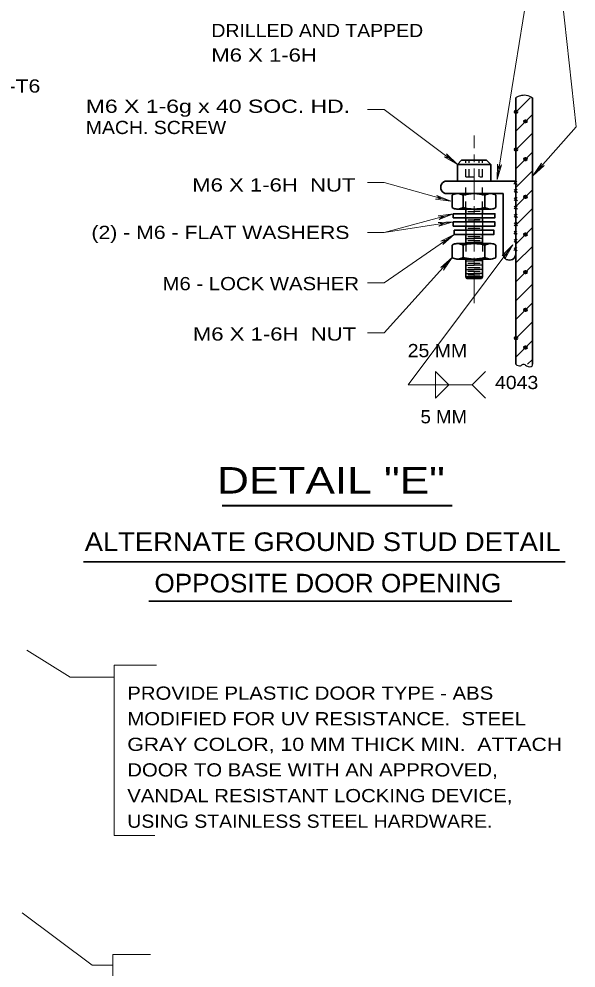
# Model space of a CAD drawing. Extents: x 312583 to 312854, y 144419 to 144597.
# Drawn here: x 312761.7 to 312793.7, y 144484.7 to 144539.3 of the extents above; entities that cross this region are included whole.
import ezdxf

# ---------------------------------------------------------------- set-up
doc = ezdxf.new("R2010")
doc.units = 0
doc.header["$LTSCALE"] = 0.3
doc.header["$PDMODE"] = 32
doc.header["$PDSIZE"] = 0.15
doc.linetypes.add('LONG_DASH_SHORT_DASH', pattern=[9.9, 6, -1.2, 1.5, -1.2])
doc.linetypes.add('SHORT_DASHED', pattern=[2.7, 1.5, -1.2])
doc.layers.add('1', color=7, linetype='Continuous', lineweight=40)
doc.layers.add('2', color=7, linetype='Continuous', lineweight=13)

msp = doc.modelspace()

# ---------------------------------------------------------------- linework, layer by layer
at = {"layer": '1', "lineweight": 35}
for p, q in [((312790.2149, 144519.4765), (312790.2149, 144534.8099)), ((312791.1732, 144519.4765), (312791.1732, 144534.8099)), ((312786.8569, 144530.0182), (312786.8569, 144530.9765)), ((312788.5359, 144531.2142), (312788.7735, 144530.9765)), ((312790.2149, 144530.0182), (312786.2589, 144530.0182)), ((312789.4942, 144529.2975), (312786.2589, 144529.2975)), ((312786.5579, 144529.2132), (312786.5579, 144528.4925)), ((312786.8339, 144529.2975), (312787.8152, 144529.2975)), ((312787.1865, 144529.2132), (312787.1865, 144528.4925)), ((312788.7965, 144529.2975), (312787.8152, 144529.2975)), ((312788.4439, 144529.2132), (312788.4439, 144528.4925)), ((312789.0725, 144529.2132), (312789.0725, 144528.4925)), ((312789.4942, 144525.8245), (312789.4942, 144529.2975)), ((312786.8339, 144528.4005), (312787.8152, 144528.4005)), ((312787.3399, 144528.3852), (312787.3399, 144528.1475)), ((312788.7965, 144528.4005), (312787.8152, 144528.4005)), ((312788.2982, 144528.3852), (312788.2982, 144528.1475)), ((312787.3399, 144527.9022), (312787.3399, 144527.6722)), ((312788.2982, 144527.9022), (312788.2982, 144527.6722)), ((312787.3399, 144527.4345), (312787.3399, 144527.1892)), ((312788.2982, 144527.4345), (312788.2982, 144527.1892)), ((312787.3399, 144526.9515), (312787.3399, 144526.4225)), ((312788.2982, 144526.9515), (312788.2982, 144526.4225)), ((312786.5579, 144526.3382), (312786.5579, 144525.6175)), ((312786.8339, 144526.4225), (312787.8152, 144526.4225)), ((312787.1865, 144526.3382), (312787.1865, 144525.6175)), ((312788.7965, 144526.4225), (312787.8152, 144526.4225)), ((312788.4439, 144526.3382), (312788.4439, 144525.6175)), ((312789.0725, 144526.3382), (312789.0725, 144525.6175)), ((312786.8339, 144525.5255), (312787.8152, 144525.5255)), ((312787.3399, 144525.5255), (312787.3399, 144524.4982)), ((312788.7965, 144525.5255), (312787.8152, 144525.5255)), ((312788.2982, 144525.5255), (312788.2982, 144524.4982)), ((312787.3399, 144524.4982), (312787.8152, 144524.4982)), ((312788.2982, 144524.4982), (312787.8152, 144524.4982))]:
    msp.add_line(p, q, dxfattribs=at)
at = {"layer": '1', "lineweight": 13}
for p, q in [((312790.2149, 144533.9742), (312791.0505, 144534.8099)), ((312790.2149, 144532.8932), (312791.1732, 144533.8515)), ((312790.2149, 144531.8045), (312791.1732, 144532.7629)), ((312790.2149, 144530.7235), (312791.1732, 144531.6819)), ((312790.2072, 144529.6349), (312791.1732, 144530.6009)), ((312790.2149, 144528.5539), (312791.1732, 144529.5122)), ((312790.2149, 144527.4729), (312791.1732, 144528.4312)), ((312790.2149, 144526.3842), (312791.1732, 144527.3425)), ((312790.2149, 144525.3032), (312791.1732, 144526.2615)), ((312790.2149, 144524.2222), (312791.1732, 144525.1729)), ((312790.2149, 144523.1335), (312791.1732, 144524.0919)), ((312790.2149, 144522.0449), (312791.1732, 144523.0109)), ((312790.2149, 144520.9639), (312791.1732, 144521.9222)), ((312790.2149, 144519.8829), (312791.1732, 144520.8412)), ((312790.8895, 144519.4765), (312791.1732, 144519.7525))]:
    msp.add_line(p, q, dxfattribs=at)
at = {"layer": '1', "linetype": 'LONG_DASH_SHORT_DASH', "lineweight": 13}
msp.add_line((312787.8152, 144522.9955), (312787.8152, 144532.6325), dxfattribs=at)
at = {"layer": '1', "linetype": 'SHORT_DASHED', "lineweight": 25}
for p, q in [((312787.3399, 144530.2559), (312787.3399, 144531.2142)), ((312787.5392, 144530.2559), (312787.5392, 144531.2142)), ((312788.1142, 144530.2559), (312788.1142, 144531.2142)), ((312788.2982, 144530.2559), (312788.2982, 144531.2142)), ((312787.3399, 144530.2559), (312788.2982, 144530.2559)), ((312787.3399, 144528.3852), (312787.3399, 144530.0182)), ((312788.2982, 144528.3852), (312788.2982, 144530.0182)), ((312787.3399, 144527.9022), (312787.3399, 144528.1475)), ((312788.2982, 144527.9022), (312788.2982, 144528.1475)), ((312787.3399, 144527.6722), (312787.3399, 144527.4345)), ((312788.2982, 144527.6722), (312788.2982, 144527.4345)), ((312787.3399, 144527.1892), (312787.3399, 144526.9515)), ((312788.2982, 144527.1892), (312788.2982, 144526.9515)), ((312787.3399, 144526.4225), (312787.3399, 144525.5255)), ((312788.2982, 144526.4225), (312788.2982, 144525.5255))]:
    msp.add_line(p, q, dxfattribs=at)
at = {"layer": '1', "lineweight": 25}
for p, q in [((312787.4549, 144528.2625), (312787.8152, 144528.2625)), ((312788.1755, 144528.2625), (312787.8152, 144528.2625)), ((312787.4549, 144527.7872), (312787.8152, 144527.7872)), ((312787.4549, 144527.7872), (312788.1755, 144527.7872)), ((312788.1755, 144527.7872), (312787.8152, 144527.7872)), ((312787.4549, 144527.3119), (312788.1755, 144527.3119)), ((312787.3322, 144526.7215), (312787.8152, 144526.7215)), ((312787.3322, 144526.4839), (312787.8152, 144526.4839)), ((312787.4549, 144526.8289), (312788.1755, 144526.8289)), ((312787.4549, 144526.5912), (312788.1755, 144526.5912)), ((312788.2982, 144526.7215), (312787.8152, 144526.7215)), ((312788.2982, 144526.4839), (312787.8152, 144526.4839)), ((312787.3322, 144525.4182), (312787.8152, 144525.4182)), ((312788.2982, 144525.4182), (312787.8152, 144525.4182)), ((312787.3322, 144525.1729), (312787.8152, 144525.1729)), ((312787.3322, 144524.9352), (312787.8152, 144524.9352)), ((312787.4549, 144525.2879), (312788.1755, 144525.2879)), ((312787.4549, 144525.0502), (312788.1755, 144525.0502)), ((312787.4549, 144524.8279), (312788.1755, 144524.8279)), ((312788.2982, 144525.1729), (312787.8152, 144525.1729)), ((312788.2982, 144524.9352), (312787.8152, 144524.9352)), ((312787.3322, 144524.6975), (312787.8152, 144524.6975)), ((312787.4549, 144524.6132), (312788.1755, 144524.6132)), ((312788.2982, 144524.6975), (312787.8152, 144524.6975))]:
    msp.add_line(p, q, dxfattribs=at)
at = {"layer": '1', "lineweight": 35}
for points in [[(312788.5359, 144531.2142), (312787.1022, 144531.2142), (312786.8569, 144530.9765)], [(312788.7735, 144530.0182), (312788.7735, 144530.9765), (312786.8569, 144530.9765)], [(312787.3399, 144524.4982), (312787.4012, 144524.4139), (312787.8152, 144524.4139)], [(312788.2982, 144524.4982), (312788.2369, 144524.4139), (312787.8152, 144524.4139)]]:
    msp.add_lwpolyline(points, dxfattribs=at)
for points in [[(312786.6192, 144528.1399), (312786.6192, 144527.9022), (312789.0189, 144527.9022), (312789.0189, 144528.1399)], [(312786.6192, 144527.6645), (312786.6192, 144527.4269), (312789.0189, 144527.4269), (312789.0189, 144527.6645)], [(312786.6805, 144527.1892), (312786.6805, 144526.9515), (312788.9575, 144526.9515), (312788.9575, 144527.1892)]]:
    msp.add_lwpolyline(points, close=True, dxfattribs=at)
for centre, radius, start, end in [((312786.257, 144529.6559), 0.3584, 89.69361, 270.30639), ((312786.8489, 144528.7785), 0.5187, 91.66257, 124.1297), ((312786.5984, 144527.8443), 1.4854, 66.63635, 78.22986), ((312787.8814, 144526.6186), 2.6807, 91.405, 105.00202), ((312787.7499, 144526.6186), 2.6807, 74.99798, 88.595), ((312789.0329, 144527.8443), 1.4854, 101.77014, 113.36365), ((312788.7824, 144528.7785), 0.5187, 55.8703, 88.33743), ((312786.8489, 144528.9215), 0.5187, 235.8703, 268.33743), ((312786.5984, 144529.8557), 1.4854, 281.77014, 293.36365), ((312787.8814, 144531.0814), 2.6807, 254.99798, 268.595), ((312787.7499, 144531.0814), 2.6807, 271.405, 285.00202), ((312789.0329, 144529.8557), 1.4854, 246.63635, 258.22986), ((312788.7824, 144528.9215), 0.5187, 271.66257, 304.1297), ((312786.8489, 144525.9035), 0.5187, 91.66257, 124.1297), ((312786.5984, 144524.9693), 1.4854, 66.63635, 78.22986), ((312787.8814, 144523.7436), 2.6807, 91.405, 105.00202), ((312787.7499, 144523.7436), 2.6807, 74.99798, 88.595), ((312789.0329, 144524.9693), 1.4854, 101.77014, 113.36365), ((312788.7824, 144525.9035), 0.5187, 55.8703, 88.33743), ((312786.8489, 144526.0465), 0.5187, 235.8703, 268.33743), ((312786.5984, 144526.9807), 1.4854, 281.77014, 293.36365), ((312787.8814, 144528.2064), 2.6807, 254.99798, 268.595), ((312787.7499, 144528.2064), 2.6807, 271.405, 285.00202), ((312789.0329, 144526.9807), 1.4854, 246.63635, 258.22986), ((312788.7824, 144526.0465), 0.5187, 271.66257, 304.1297), ((312789.8526, 144525.8226), 0.3584, 179.69361, 0.30639)]:
    msp.add_arc(centre, radius, start, end, dxfattribs=at)
at = {"layer": '1', "lineweight": 25}
for points in [[(312790.2149, 144534.8099), (312790.3682, 144534.9019), (312790.6365, 144534.9632), (312790.8129, 144534.9632), (312791.1732, 144534.8099)], [(312790.2149, 144519.4765), (312790.4909, 144519.3922), (312790.6365, 144519.4765), (312790.8359, 144519.3922), (312791.1579, 144519.3922), (312791.1732, 144519.4765)]]:
    msp.add_spline(points, degree=3, dxfattribs=at)
at = {"layer": '1'}
for p in [(312790.2302, 144533.9972), (312790.7745, 144533.4529), (312790.2302, 144531.8275), (312790.7745, 144531.2832), (312790.7745, 144529.1135), (312790.7745, 144526.9439), (312790.7745, 144524.7742), (312790.7745, 144522.6122), (312790.2302, 144520.9792), (312790.7745, 144520.4425)]:
    msp.add_point(p, dxfattribs=at)
at = {"layer": '2'}
for p, q in [((312789.1415, 144530.1102), (312790.9202, 144541.0582)), ((312782.6479, 144534.1429), (312781.6895, 144534.1429)), ((312782.6479, 144534.1429), (312786.8569, 144530.9765)), ((312786.1055, 144531.4135), (312786.3892, 144531.3292)), ((312786.8569, 144530.9765), (312786.1055, 144531.4135)), ((312786.2282, 144531.5822), (312786.3892, 144531.3292)), ((312786.8569, 144530.9765), (312786.2282, 144531.5822)), ((312789.1415, 144530.1102), (312789.1722, 144530.9842)), ((312789.1415, 144530.1102), (312789.3869, 144530.9459)), ((312789.1722, 144530.9842), (312789.2412, 144530.6929)), ((312789.3869, 144530.9459), (312789.2412, 144530.6929)), ((312791.2039, 144530.3249), (312791.6945, 144531.0455)), ((312791.2039, 144530.3249), (312791.8555, 144530.9075)), ((312791.6945, 144531.0455), (312791.5949, 144530.7695)), ((312791.8555, 144530.9075), (312791.5949, 144530.7695)), ((312782.6479, 144529.9262), (312781.6895, 144529.9262)), ((312782.6479, 144529.9262), (312786.4735, 144528.8529)), ((312785.6685, 144529.1902), (312785.9062, 144529.0139)), ((312786.4735, 144528.8529), (312785.6685, 144529.1902)), ((312785.6072, 144528.9832), (312785.9062, 144529.0139)), ((312786.4735, 144528.8529), (312785.6072, 144528.9832)), ((312782.6479, 144527.0589), (312786.6192, 144528.1399)), ((312786.6192, 144528.1399), (312785.7605, 144528.0172)), ((312786.6192, 144528.1399), (312785.8142, 144527.8102)), ((312782.6479, 144527.0589), (312786.6192, 144527.6645)), ((312786.6192, 144527.6645), (312785.7452, 144527.6415)), ((312786.6192, 144527.6645), (312785.7452, 144527.6415)), ((312785.7452, 144527.6415), (312786.0365, 144527.5802)), ((312785.7452, 144527.6415), (312786.0365, 144527.5802)), ((312785.7605, 144528.0172), (312786.0519, 144527.9865)), ((312786.6192, 144527.6645), (312785.7835, 144527.4269)), ((312786.6192, 144527.6645), (312785.7835, 144527.4269)), ((312785.7835, 144527.4269), (312786.0365, 144527.5802)), ((312785.7835, 144527.4269), (312786.0365, 144527.5802)), ((312785.8142, 144527.8102), (312786.0519, 144527.9865)), ((312782.6479, 144527.0589), (312781.6895, 144527.0589)), ((312782.6479, 144524.1685), (312786.6805, 144526.9515)), ((312786.6805, 144526.9515), (312785.9062, 144526.5529)), ((312785.9062, 144526.5529), (312786.1975, 144526.6219)), ((312786.6805, 144526.9515), (312786.0289, 144526.3765)), ((312786.0289, 144526.3765), (312786.1975, 144526.6219)), ((312784.0279, 144518.2882), (312790.0462, 144526.3535)), ((312790.0462, 144526.3535), (312789.4405, 144525.7249)), ((312790.0462, 144526.3535), (312789.4405, 144525.7249)), ((312790.0462, 144526.3535), (312789.6169, 144525.5945)), ((312790.0462, 144526.3535), (312789.6169, 144525.5945)), ((312782.6479, 144521.2782), (312786.5579, 144525.6175)), ((312786.5579, 144525.6175), (312785.8985, 144525.0425)), ((312786.5579, 144525.6175), (312786.0595, 144524.8969)), ((312789.4405, 144525.7249), (312789.6935, 144525.8782)), ((312789.4405, 144525.7249), (312789.6935, 144525.8782)), ((312789.6169, 144525.5945), (312789.6935, 144525.8782)), ((312789.6169, 144525.5945), (312789.6935, 144525.8782)), ((312785.8985, 144525.0425), (312786.1669, 144525.1805)), ((312786.0595, 144524.8969), (312786.1669, 144525.1805)), ((312782.6479, 144524.1685), (312781.6895, 144524.1685)), ((312782.6479, 144521.2782), (312781.6895, 144521.2782)), ((312788.4822, 144519.0549), (312787.7155, 144518.2882)), ((312784.0279, 144518.2882), (312787.7155, 144518.2882)), ((312788.4822, 144517.5215), (312787.7155, 144518.2882)), ((312764.5889, 144501.4672), (312762.0972, 144503.0236)), ((312767.1265, 144502.1649), (312769.5492, 144502.1649)), ((312767.1265, 144492.3592), (312767.1265, 144502.1649)), ((312767.1265, 144501.4672), (312764.5889, 144501.4672)), ((312767.1265, 144492.3592), (312769.4572, 144492.3592)), ((312765.8578, 144484.9149), (312761.8251, 144487.9202)), ((312765.8578, 144484.9149), (312767.0538, 144484.9149))]:
    msp.add_line(p, q, dxfattribs=at)
at = {"layer": '2', "lineweight": 25}
for p, q in [((312790.1075, 144529.8342), (312790.2839, 144530.0105)), ((312790.2915, 144529.8189), (312790.1152, 144529.9952)), ((312790.1152, 144529.3742), (312790.2915, 144529.5505)), ((312790.3069, 144529.3589), (312790.1229, 144529.5352)), ((312790.1152, 144528.8912), (312790.2915, 144529.0752)), ((312790.3069, 144528.8835), (312790.1229, 144529.0599)), ((312790.1152, 144528.4159), (312790.2915, 144528.5922)), ((312790.3069, 144528.4005), (312790.1229, 144528.5769)), ((312790.1229, 144527.9329), (312790.2992, 144528.1092)), ((312790.3069, 144527.9175), (312790.1305, 144528.0939)), ((312790.1229, 144527.4499), (312790.2915, 144527.6262)), ((312790.3069, 144527.4345), (312790.1229, 144527.6109)), ((312790.1152, 144526.9669), (312790.2839, 144527.1509)), ((312790.2992, 144526.9592), (312790.1152, 144527.1355)), ((312790.1152, 144526.4992), (312790.2915, 144526.6755)), ((312790.2992, 144526.4839), (312790.1229, 144526.6602)), ((312790.1075, 144526.0162), (312790.2839, 144526.2002)), ((312790.2915, 144526.0085), (312790.1152, 144526.1772))]:
    msp.add_line(p, q, dxfattribs=at)
at = {"layer": '2', "lineweight": 40}
msp.add_line((312773.3372, 144511.3499), (312786.5554, 144511.3499), dxfattribs=at)
at = {"layer": '2', "lineweight": 35}
for p, q in [((312765.3663, 144508.1145), (312793.0506, 144508.1145)), ((312769.1218, 144505.8529), (312789.9909, 144505.8529))]:
    msp.add_line(p, q, dxfattribs=at)
at = {"layer": '2'}
for points in [[(312790.0124, 144545.4282), (312792.3539, 144545.4282), (312793.6802, 144533.1385), (312791.2039, 144530.3249)], [(312785.6072, 144518.2882), (312785.6072, 144519.0549), (312786.3739, 144518.2882)], [(312785.6072, 144518.2882), (312785.6072, 144517.5215), (312786.3739, 144518.2882)], [(312767.0538, 144477.1562), (312767.0538, 144485.5282), (312769.2158, 144485.5282)]]:
    msp.add_lwpolyline(points, dxfattribs=at)

# ---------------------------------------------------------------- texts
for s, height, width, p in [('DRILLED AND TAPPED', 0.76, 1.1, (312772.7148, 144538.2981)), ('M6 X 1-6H', 0.76, 1.25, (312772.7072, 144536.8875)), ('ALLOY 356-T6', 0.76, 1.2, (312754.7425, 144535.1062)), ('M6 X 1-6g x 40 SOC. HD.', 0.76, 1.3, (312765.4898, 144533.9415)), ('MACH. SCREW ', 0.76, 1.1, (312765.4898, 144532.7215)), ('M6 X 1-6H  NUT', 0.76, 1.25, (312771.6119, 144529.4155)), ('(2) - M6 - FLAT WASHERS', 0.76, 1.2, (312765.8143, 144526.6843)), ('M6 - LOCK WASHER', 0.76, 1.15, (312769.9041, 144523.7374)), ('M6 X 1-6H  NUT', 0.76, 1.25, (312771.6492, 144520.8394)), ('25 MM', 0.76, 1.1, (312784.0028, 144519.8849)), ('4043', 0.76, 1.1, (312789.0218, 144518.0486)), ('5 MM', 0.76, 1.05, (312784.7409, 144516.0792)), (' DETAIL "E"', 1.52, 1.25, (312772.3338, 144512.0403)), ('ALTERNATE GROUND STUD DETAIL', 1.07, 1.1, (312765.4293, 144508.7345)), ('OPPOSITE DOOR OPENING', 1.07, 1.05, (312769.4398, 144506.352)), ('PROVIDE PLASTIC DOOR TYPE - ABS', 0.76, 1.15, (312767.8779, 144500.1782)), ('MODIFIED FOR UV RESISTANCE.  STEEL', 0.76, 1.15, (312767.8779, 144498.7062)), ('GRAY COLOR, 10 MM THICK MIN.  ATTACH', 0.76, 1.2, (312767.8779, 144497.2342)), ('DOOR TO BASE WITH AN APPROVED,', 0.76, 1.15, (312767.8779, 144495.7622)), ('VANDAL RESISTANT LOCKING DEVICE,', 0.76, 1.15, (312767.8779, 144494.2826)), ('USING STAINLESS STEEL HARDWARE.', 0.76, 1.1, (312767.8779, 144492.8106))]:
    msp.add_text(s, height=height, dxfattribs=dict(at, width=width)).set_placement(p)

doc.saveas('drawing.dxf')
